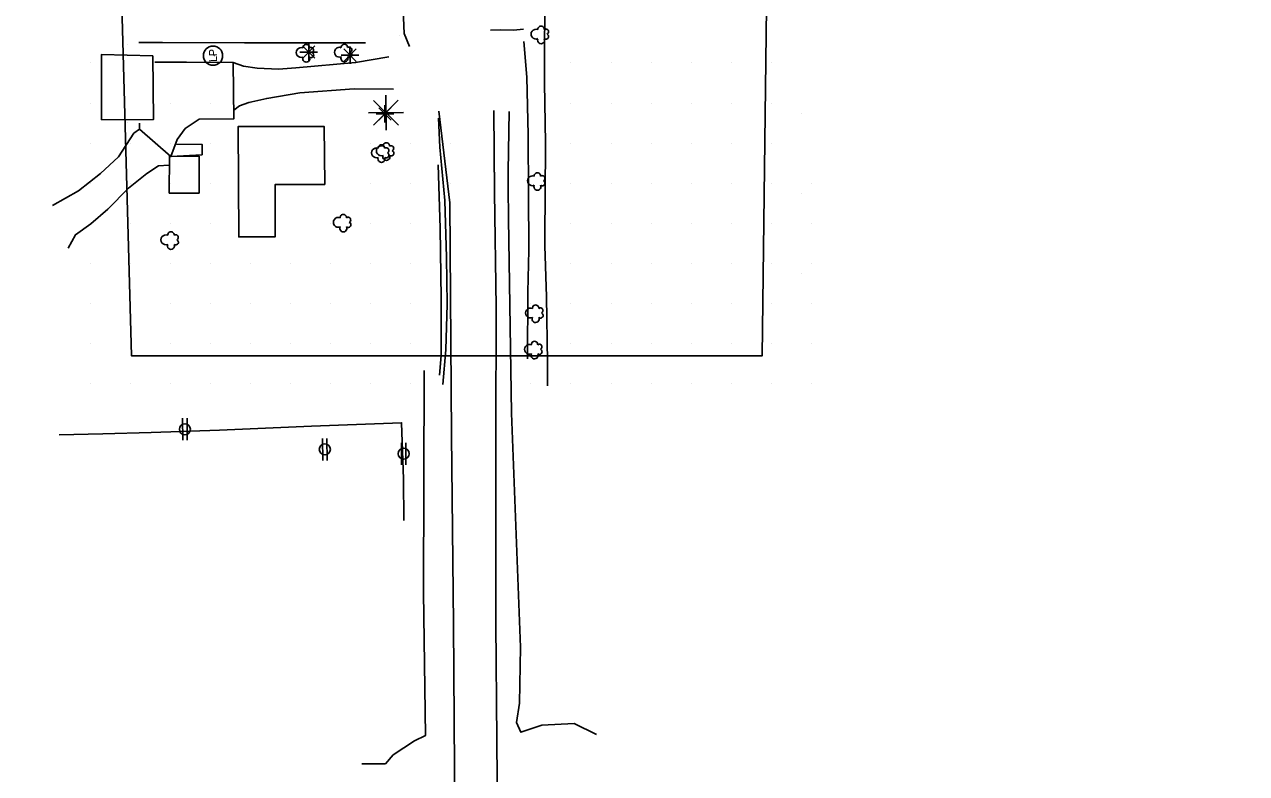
# Model space of a CAD drawing. Extents: x 19528164 to 19545171, y 7585743 to 7602745.
# Drawn here: x 19534872 to 19535482, y 7586070 to 7586444 of the extents above; entities that cross this region are included whole.
import ezdxf

# ---------------------------------------------------------------- set-up
doc = ezdxf.new("R2010")
doc.units = 0
for name, color, linetype in [('Default', 7, 'Continuous'), ('PhoBreakLine', 7, 'Continuous'), ('PhoBuilding', 7, 'Continuous'), ('PhoDrainageArrow', 7, 'Continuous'), ('PhoEdgeSidewalk', 7, 'Continuous'), ('PhoFence', 7, 'Continuous'), ('PhoISAEPoints', 7, 'Continuous'), ('PhoSurveyLimits', 7, 'Continuous'), ('PhoVegetation', 7, 'Continuous'), ('SurBreakLine', 7, 'Continuous'), ('SurEdgeEntranceUnpaved', 7, 'Continuous'), ('SurNaturalCells', 7, 'Continuous'), ('SurROWRail', 7, 'Continuous')]:
    doc.layers.add(name, color=color, linetype=linetype)

# ---------------------------------------------------------------- blocks, each defined once
blk = doc.blocks.new('TREV')
at = {"layer": 'Default'}
for p, q in [((-6.18, -6.19), (6.19, 6.18)), ((6.18, -6.18), (-6.18, 6.18)), ((0, -8.75), (0, 8.75)), ((-8.75, 0), (8.75, 0)), ((0, 0), (0, 0))]:
    blk.add_line(p, q, dxfattribs=at)
blk = doc.blocks.new('TRDC')
at = {"layer": 'PhoVegetation'}
for centre, radius, start, end in [((-6, -1.1), 3.52, 65.4824, 294.5175), ((0.1, 4), 4.92, 338.2051, 201.7949), ((4.9, -1.1), 3.21, 265.9982, 94.0018), ((-2.4, -5.9), 2.68, 142.7501, 335.3223), ((2.5, -5.8), 2.67, 206.5242, 35.4033)]:
    blk.add_arc(centre, radius, start, end, dxfattribs=at)

msp = doc.modelspace()

# ---------------------------------------------------------------- linework, layer by layer
at = {"layer": 'PhoBreakLine'}
for points in [[(19535064.28, 7586433.3), (19535061.65, 7586439.66), (19535060.28, 7586471.38), (19535060.21, 7586516.13), (19535058, 7586546.32), (19535059.3, 7586590.84), (19535058.14, 7586640.62), (19535058.3, 7586700.75), (19535057.51, 7586715.23)], [(19535128.24, 7586717.22), (19535128.6, 7586669.51), (19535129.76, 7586616.79), (19535131.3, 7586566.06), (19535131.17, 7586522.66), (19535131.89, 7586467.33), (19535131.84, 7586415.15), (19535132.24, 7586384.99), (19535132.07, 7586358.82)], [(19535123.73, 7586359.2), (19535123.57, 7586389.06), (19535123.02, 7586417.99), (19535121.37, 7586435.81)], [(19535080.96, 7586264.36), (19535082.44, 7586281.74), (19535083.16, 7586304.54), (19535082.86, 7586327.81), (19535082.03, 7586356.24), (19535079.53, 7586383.02), (19535078.78, 7586397.49)], [(19535106.54, 7586401.21), (19535106.87, 7586359.97)], [(19535078.63, 7586374.19), (19535079.73, 7586342.46), (19535080.1, 7586307.35), (19535080.17, 7586278.84), (19535079.31, 7586269.11)], [(19535123.88, 7586331.43), (19535123.39, 7586310.52), (19535123.3, 7586277.28)], [(19535131.9, 7586333.69), (19535132.85, 7586308.17), (19535133.26, 7586275.57), (19535133.31, 7586263.67)]]:
    msp.add_lwpolyline(points, dxfattribs=at)
at = {"layer": 'PhoBuilding'}
for points in [[(19534936.09, 7586428.58), (19534936.52, 7586396.77), (19534910.48, 7586396.68), (19534910.46, 7586429.17), (19534910.51, 7586429.17), (19534936.09, 7586428.58)], [(19534929.52, 7586394.99), (19534929.49, 7586391.99), (19534945.16, 7586378.23), (19534948.25, 7586386.77), (19534952.26, 7586392.22), (19534959.23, 7586397), (19534976.51, 7586397.06), (19534976.23, 7586425.23), (19534952.89, 7586425.46), (19534937.19, 7586425.43)]]:
    msp.add_lwpolyline(points, dxfattribs=at)
for points in [[(19535022.02, 7586364.33), (19534997.19, 7586364.24), (19534997.29, 7586338.16), (19534979.05, 7586338.1), (19534978.81, 7586393.33), (19535021.65, 7586393.32)], [(19534944.31, 7586359.97), (19534959.23, 7586360.02), (19534959.21, 7586378.38), (19534944.41, 7586378.33)]]:
    msp.add_lwpolyline(points, close=True, dxfattribs=at)
at = {"layer": 'PhoDrainageArrow'}
for points in [[(19535114.18, 7586400.71), (19535113.63, 7586370.88), (19535113.67, 7586359.66)], [(19535114.18, 7586400.71), (19535114.16, 7586400.14)]]:
    msp.add_lwpolyline(points, dxfattribs=at)
at = {"layer": 'PhoEdgeSidewalk'}
msp.add_lwpolyline([(19534948.01, 7586384.46), (19534960.75, 7586384.36), (19534960.75, 7586379.14), (19534945.16, 7586378.23)], dxfattribs=at)
at = {"layer": 'PhoFence'}
msp.add_line((19535042.36, 7586435.05), (19535004.2, 7586435.13), dxfattribs=at)
for points in [[(19535004.2, 7586435.13), (19534981.9, 7586435.08), (19534940.88, 7586435.21), (19534929.12, 7586435.3)], [(19534889.29, 7586239.25), (19534911.16, 7586239.74), (19534935.35, 7586240.34), (19534969.38, 7586241.51), (19535015.31, 7586243.5), (19535060.38, 7586245.32), (19535061.34, 7586217.1), (19535061.48, 7586196.53)]]:
    msp.add_lwpolyline(points, dxfattribs=at)
at = {"layer": 'PhoISAEPoints'}
for p, q in [((19535145, 7586425), (19535145, 7586425)), ((19535165, 7586425), (19535165, 7586425)), ((19535145, 7586405), (19535145, 7586405)), ((19535165, 7586405), (19535165, 7586405)), ((19535045, 7586385), (19535045, 7586385)), ((19535065, 7586385), (19535065, 7586385)), ((19535085, 7586385), (19535085, 7586385)), ((19535145, 7586385), (19535145, 7586385)), ((19535165, 7586385), (19535165, 7586385)), ((19535045, 7586365), (19535045, 7586365)), ((19535065, 7586365), (19535065, 7586365)), ((19535085, 7586365), (19535085, 7586365)), ((19535145, 7586365), (19535145, 7586365))]:
    msp.add_line(p, q, dxfattribs=at)
at = {"layer": 'PhoSurveyLimits'}
msp.add_lwpolyline([(19533878.26, 7590287.69), (19534414.23, 7589271.02), (19534620.47, 7588835.55), (19535976.6, 7587917.86), (19535872.2, 7587743.02), (19536196.76, 7587523.02), (19536087.66, 7587353.22), (19535761.89, 7587557.7), (19535245.62, 7586693.59), (19535240.5, 7586278.66), (19534925.52, 7586278.66), (19534905.11, 7587015.02), (19534733.57, 7587498.57), (19533471.56, 7588328.44)], dxfattribs=at)
at = {"layer": 'PhoVegetation'}
for p, q in [((19535014, 7586426.04), (19535013.97, 7586434.79)), ((19535018.36, 7586430.43), (19535009.61, 7586430.4)), ((19535017.09, 7586427.34), (19535010.88, 7586433.5)), ((19535017.07, 7586433.52), (19535010.9, 7586427.31)), ((19535013.99, 7586430.42), (19535013.99, 7586430.42)), ((19535039, 7586428.92), (19535030.26, 7586428.89)), ((19535037.73, 7586425.82), (19535031.53, 7586431.99)), ((19535037.71, 7586432.01), (19535031.55, 7586425.8)), ((19535034.65, 7586424.53), (19535034.61, 7586433.28)), ((19535034.63, 7586428.9), (19535034.63, 7586428.9)), ((19535052.07, 7586395.2), (19535052.04, 7586403.95)), ((19535056.43, 7586399.59), (19535047.68, 7586399.56)), ((19535055.16, 7586396.49), (19535048.95, 7586402.65)), ((19535055.14, 7586402.68), (19535048.98, 7586396.47)), ((19535052.06, 7586399.57), (19535052.06, 7586399.57))]:
    msp.add_line(p, q, dxfattribs=at)
for centre, radius, start, end in [((19535047.82, 7586380.12), 2.46, 68.40922, 291.99907), ((19535050.32, 7586382.53), 1.6, 356.20234, 184.20595), ((19535052.7, 7586381.33), 1.34, 296.72831, 125.60749), ((19535052.75, 7586378.92), 1.34, 232.95429, 65.52648), ((19535050.34, 7586377.12), 1.76, 155.68654, 24.72168), ((19535125.74, 7586366.17), 2.46, 68.40922, 291.99907), ((19535128.24, 7586368.57), 1.6, 356.20234, 184.20595), ((19535130.62, 7586367.38), 1.34, 296.72831, 125.60749), ((19535128.26, 7586363.16), 1.76, 155.68654, 24.72168), ((19535130.67, 7586364.97), 1.34, 232.95429, 65.52648), ((19535031.27, 7586347.78), 1.6, 356.20234, 184.20595), ((19535028.76, 7586345.37), 2.46, 68.40922, 291.99907), ((19535031.29, 7586342.37), 1.76, 155.68654, 24.72168), ((19535033.65, 7586346.59), 1.34, 296.72831, 125.60749), ((19535033.69, 7586344.17), 1.34, 232.95429, 65.52648), ((19534942.63, 7586336.67), 2.46, 68.40922, 291.99907), ((19534945.13, 7586339.08), 1.6, 356.20234, 184.20595), ((19534947.51, 7586337.89), 1.34, 296.72831, 125.60749), ((19534947.56, 7586335.47), 1.34, 232.95429, 65.52648), ((19534945.15, 7586333.67), 1.76, 155.68654, 24.72168), ((19535124.81, 7586300.12), 2.46, 68.40922, 291.99907), ((19535127.32, 7586302.52), 1.6, 356.20234, 184.20595), ((19535129.7, 7586301.33), 1.34, 296.72831, 125.60749), ((19535129.74, 7586298.92), 1.34, 232.95429, 65.52648), ((19535127.34, 7586297.11), 1.76, 155.68654, 24.72168), ((19535124.28, 7586281.97), 2.46, 68.40922, 291.99907), ((19535126.79, 7586284.37), 1.6, 356.20234, 184.20595), ((19535129.17, 7586283.18), 1.34, 296.72831, 125.60749), ((19535129.21, 7586280.77), 1.34, 232.95429, 65.52648), ((19535126.81, 7586278.96), 1.76, 155.68654, 24.72168)]:
    msp.add_arc(centre, radius, start, end, dxfattribs=at)
at = {"layer": 'SurBreakLine'}
for p, q in [((19535059.53, 7586438.8), (19535059.53, 7586438.8)), ((19535122.08, 7586429.8), (19535122.08, 7586429.8))]:
    msp.add_line(p, q, dxfattribs=at)
for points in [[(19535104.75, 7586441.34), (19535109.61, 7586441.55), (19535116.35, 7586441.32), (19535121.33, 7586441.87)], [(19535121.44, 7586435.05), (19535121.37, 7586435.81)], [(19535089.44, 7585742.98), (19535087.57, 7585819.4), (19535088.36, 7585924.17), (19535087.19, 7586024.5), (19535086.29, 7586144.91), (19535085.31, 7586239.16), (19535084.56, 7586355.11), (19535079.06, 7586400.98)], [(19535106.54, 7586401.21), (19535106.87, 7586360.33), (19535107.56, 7586302.98)], [(19535114.18, 7586400.71), (19535114.14, 7586399.03)], [(19535113.66, 7586362.75), (19535113.73, 7586347.11)], [(19535132.1, 7586364.53), (19535131.9, 7586333.69)], [(19535123.88, 7586331.43), (19535123.73, 7586360.3)], [(19535113.73, 7586347.11), (19535115.29, 7586250.06), (19535119.72, 7586133.12), (19535119.35, 7586105.19), (19535117.76, 7586095.6), (19535119.96, 7586090.67), (19535130.38, 7586094.14), (19535146.63, 7586095.11), (19535157.76, 7586089.62)], [(19535107.56, 7586302.98), (19535107.49, 7586239.71), (19535107.49, 7586145.08), (19535108.48, 7586028.4), (19535110.25, 7585895.04), (19535111.33, 7585757.35)], [(19535040.45, 7586074.83), (19535052.32, 7586074.86), (19535056.1, 7586079.32), (19535066.89, 7586086.38), (19535072.28, 7586089.02), (19535071.34, 7586160.56), (19535071.69, 7586271.3)]]:
    msp.add_lwpolyline(points, dxfattribs=at)
at = {"layer": 'SurEdgeEntranceUnpaved'}
for p, q in [((19534923.32, 7586434.02), (19534923.32, 7586434.02)), ((19534905, 7586425), (19534905, 7586425)), ((19534945, 7586425), (19534945, 7586425)), ((19534965, 7586425), (19534965, 7586425)), ((19534985, 7586425), (19534985, 7586425)), ((19535145, 7586425), (19535145, 7586425)), ((19535165, 7586425), (19535165, 7586425)), ((19535185, 7586425), (19535185, 7586425)), ((19535205, 7586425), (19535205, 7586425)), ((19535225, 7586425), (19535225, 7586425)), ((19535245, 7586425), (19535245, 7586425)), ((19534905, 7586405), (19534905, 7586405)), ((19534945, 7586405), (19534945, 7586405)), ((19534965, 7586405), (19534965, 7586405)), ((19534985, 7586405), (19534985, 7586405)), ((19535145, 7586405), (19535145, 7586405)), ((19535165, 7586405), (19535165, 7586405)), ((19535185, 7586405), (19535185, 7586405)), ((19535205, 7586405), (19535205, 7586405)), ((19535225, 7586405), (19535225, 7586405)), ((19535245, 7586405), (19535245, 7586405)), ((19535260, 7586400), (19535260, 7586400)), ((19534923.44, 7586395.3), (19534923.44, 7586395.3)), ((19534905, 7586385), (19534905, 7586385)), ((19534925, 7586385), (19534925, 7586385)), ((19534945, 7586385), (19534945, 7586385)), ((19534965, 7586385), (19534965, 7586385)), ((19535045, 7586385), (19535045, 7586385)), ((19535065, 7586385), (19535065, 7586385)), ((19535145, 7586385), (19535145, 7586385)), ((19535165, 7586385), (19535165, 7586385)), ((19535185, 7586385), (19535185, 7586385)), ((19535205, 7586385), (19535205, 7586385)), ((19535225, 7586385), (19535225, 7586385)), ((19535245, 7586385), (19535245, 7586385)), ((19534905, 7586365), (19534905, 7586365)), ((19534925, 7586365), (19534925, 7586365)), ((19534945, 7586365), (19534945, 7586365)), ((19534965, 7586365), (19534965, 7586365)), ((19535045, 7586365), (19535045, 7586365)), ((19535065, 7586365), (19535065, 7586365)), ((19535145, 7586365), (19535145, 7586365)), ((19535165, 7586365), (19535165, 7586365)), ((19535185, 7586365), (19535185, 7586365)), ((19535205, 7586365), (19535205, 7586365)), ((19535225, 7586365), (19535225, 7586365)), ((19535245, 7586365), (19535245, 7586365)), ((19535265, 7586365), (19535265, 7586365)), ((19535260, 7586360), (19535260, 7586360)), ((19534905, 7586345), (19534905, 7586345)), ((19534925, 7586345), (19534925, 7586345)), ((19534945, 7586345), (19534945, 7586345)), ((19534965, 7586345), (19534965, 7586345)), ((19535025, 7586345), (19535025, 7586345)), ((19535045, 7586345), (19535045, 7586345)), ((19535065, 7586345), (19535065, 7586345)), ((19535145, 7586345), (19535145, 7586345)), ((19535165, 7586345), (19535165, 7586345)), ((19535185, 7586345), (19535185, 7586345)), ((19535205, 7586345), (19535205, 7586345)), ((19535225, 7586345), (19535225, 7586345)), ((19535245, 7586345), (19535245, 7586345)), ((19535265, 7586345), (19535265, 7586345)), ((19534905, 7586325), (19534905, 7586325)), ((19534925, 7586325), (19534925, 7586325)), ((19534945, 7586325), (19534945, 7586325)), ((19534965, 7586325), (19534965, 7586325)), ((19534985, 7586325), (19534985, 7586325)), ((19535005, 7586325), (19535005, 7586325)), ((19535025, 7586325), (19535025, 7586325)), ((19535045, 7586325), (19535045, 7586325)), ((19535065, 7586325), (19535065, 7586325)), ((19535145, 7586325), (19535145, 7586325)), ((19535165, 7586325), (19535165, 7586325)), ((19535185, 7586325), (19535185, 7586325)), ((19535205, 7586325), (19535205, 7586325)), ((19535225, 7586325), (19535225, 7586325)), ((19535245, 7586325), (19535245, 7586325)), ((19535265, 7586325), (19535265, 7586325)), ((19535260, 7586320), (19535260, 7586320)), ((19534905, 7586305), (19534905, 7586305)), ((19534925, 7586305), (19534925, 7586305)), ((19534945, 7586305), (19534945, 7586305)), ((19534965, 7586305), (19534965, 7586305)), ((19534985, 7586305), (19534985, 7586305)), ((19535005, 7586305), (19535005, 7586305)), ((19535025, 7586305), (19535025, 7586305)), ((19535045, 7586305), (19535045, 7586305)), ((19535065, 7586305), (19535065, 7586305)), ((19535125, 7586305), (19535125, 7586305)), ((19535145, 7586305), (19535145, 7586305)), ((19535165, 7586305), (19535165, 7586305)), ((19535185, 7586305), (19535185, 7586305)), ((19535205, 7586305), (19535205, 7586305)), ((19535225, 7586305), (19535225, 7586305)), ((19535245, 7586305), (19535245, 7586305)), ((19535265, 7586305), (19535265, 7586305)), ((19534905, 7586285), (19534905, 7586285)), ((19534925, 7586285), (19534925, 7586285)), ((19534945, 7586285), (19534945, 7586285)), ((19534965, 7586285), (19534965, 7586285)), ((19534985, 7586285), (19534985, 7586285)), ((19535005, 7586285), (19535005, 7586285)), ((19535025, 7586285), (19535025, 7586285)), ((19535045, 7586285), (19535045, 7586285)), ((19535065, 7586285), (19535065, 7586285)), ((19535125, 7586285), (19535125, 7586285)), ((19535145, 7586285), (19535145, 7586285)), ((19535165, 7586285), (19535165, 7586285)), ((19535185, 7586285), (19535185, 7586285)), ((19535205, 7586285), (19535205, 7586285)), ((19535225, 7586285), (19535225, 7586285)), ((19535245, 7586285), (19535245, 7586285)), ((19535265, 7586285), (19535265, 7586285)), ((19534905, 7586265), (19534905, 7586265)), ((19534925, 7586265), (19534925, 7586265)), ((19534945, 7586265), (19534945, 7586265)), ((19534965, 7586265), (19534965, 7586265)), ((19534985, 7586265), (19534985, 7586265)), ((19535005, 7586265), (19535005, 7586265)), ((19535025, 7586265), (19535025, 7586265)), ((19535045, 7586265), (19535045, 7586265)), ((19535065, 7586265), (19535065, 7586265)), ((19535125, 7586265), (19535125, 7586265)), ((19535145, 7586265), (19535145, 7586265)), ((19535165, 7586265), (19535165, 7586265)), ((19535185, 7586265), (19535185, 7586265)), ((19535205, 7586265), (19535205, 7586265)), ((19535225, 7586265), (19535225, 7586265)), ((19535245, 7586265), (19535245, 7586265)), ((19535265, 7586265), (19535265, 7586265))]:
    msp.add_line(p, q, dxfattribs=at)
at = {"layer": 'SurNaturalCells'}
for p, q in [((19534951.04, 7586236.51), (19534951, 7586247.51)), ((19534953.24, 7586236.52), (19534953.2, 7586247.52)), ((19535020.96, 7586226.48), (19535020.92, 7586237.47)), ((19535023.16, 7586226.48), (19535023.12, 7586237.48)), ((19535060.33, 7586224.3), (19535060.29, 7586235.3)), ((19535062.53, 7586224.31), (19535062.49, 7586235.31))]:
    msp.add_line(p, q, dxfattribs=at)
for centre, radius in [((19534966.19, 7586428.65), 4.8), ((19534966.87, 7586428.64), 0.008), ((19534952.12, 7586242.01), 2.76), ((19535022.04, 7586231.98), 2.76), ((19535061.41, 7586229.81), 2.76)]:
    msp.add_circle(centre, radius, dxfattribs=at)
at = {"layer": 'SurROWRail'}
for points in [[(19535007.52, 7586422.62), (19535037.39, 7586425.2), (19535054.03, 7586428.09)], [(19535007.52, 7586422.62), (19534998.97, 7586421.93), (19534988.29, 7586422.37), (19534981.33, 7586423.33), (19534976.23, 7586425.23)], [(19534976.66, 7586401.42), (19534979.41, 7586403.65), (19534984.08, 7586405.22), (19534993.01, 7586407.29), (19535009.62, 7586410.07)], [(19535056.28, 7586411.93), (19535036.67, 7586412.07), (19535009.62, 7586410.07)], [(19534885.92, 7586353.86), (19534899.01, 7586361.2), (19534910.01, 7586369.77), (19534919, 7586378.12), (19534926.55, 7586389.88), (19534929.49, 7586391.99)], [(19534944.07, 7586373.91), (19534938.93, 7586373.61), (19534933.05, 7586369.75), (19534923.92, 7586362.42), (19534913.67, 7586351.92), (19534905.08, 7586344.62), (19534897.56, 7586339.17), (19534893.8, 7586332.51)]]:
    msp.add_lwpolyline(points, dxfattribs=at)

# ---------------------------------------------------------------- block references
at = {"layer": 'PhoVegetation', "rotation": 90.20414764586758}
for name, p, xscale, yscale in [('TRDC', (19535129.53, 7586439.39), 0.4999999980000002, 0.49999999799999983), ('TRDC', (19535129.53, 7586439.39), 0.4999999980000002, 0.49999999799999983), ('TRDC', (19535012.19, 7586430.17), 0.4999999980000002, 0.49999999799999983), ('TRDC', (19535012.19, 7586430.17), 0.4999999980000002, 0.49999999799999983), ('TRDC', (19535031.29, 7586430.32), 0.4999999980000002, 0.49999999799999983), ('TRDC', (19535031.29, 7586430.32), 0.4999999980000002, 0.49999999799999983), ('TREV', (19535052.59, 7586400.16), 0.9999999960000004, 0.9999999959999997), ('TREV', (19535052.59, 7586400.16), 0.9999999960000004, 0.9999999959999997), ('TRDC', (19535052.23, 7586381.09), 0.4999999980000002, 0.49999999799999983), ('TRDC', (19535052.23, 7586381.09), 0.4999999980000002, 0.49999999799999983)]:
    msp.add_blockref(name, p, dxfattribs=dict(at, xscale=xscale, yscale=yscale))

# ---------------------------------------------------------------- texts
at = {"layer": 'SurNaturalCells'}
for height, p in [(3.999, (19534968.2, 7586425.48)), (0.00667, (19534966.88, 7586428.64))]:
    msp.add_text('LP', height=height, rotation=90.20415, dxfattribs=at).set_placement(p)

doc.saveas('drawing.dxf')
